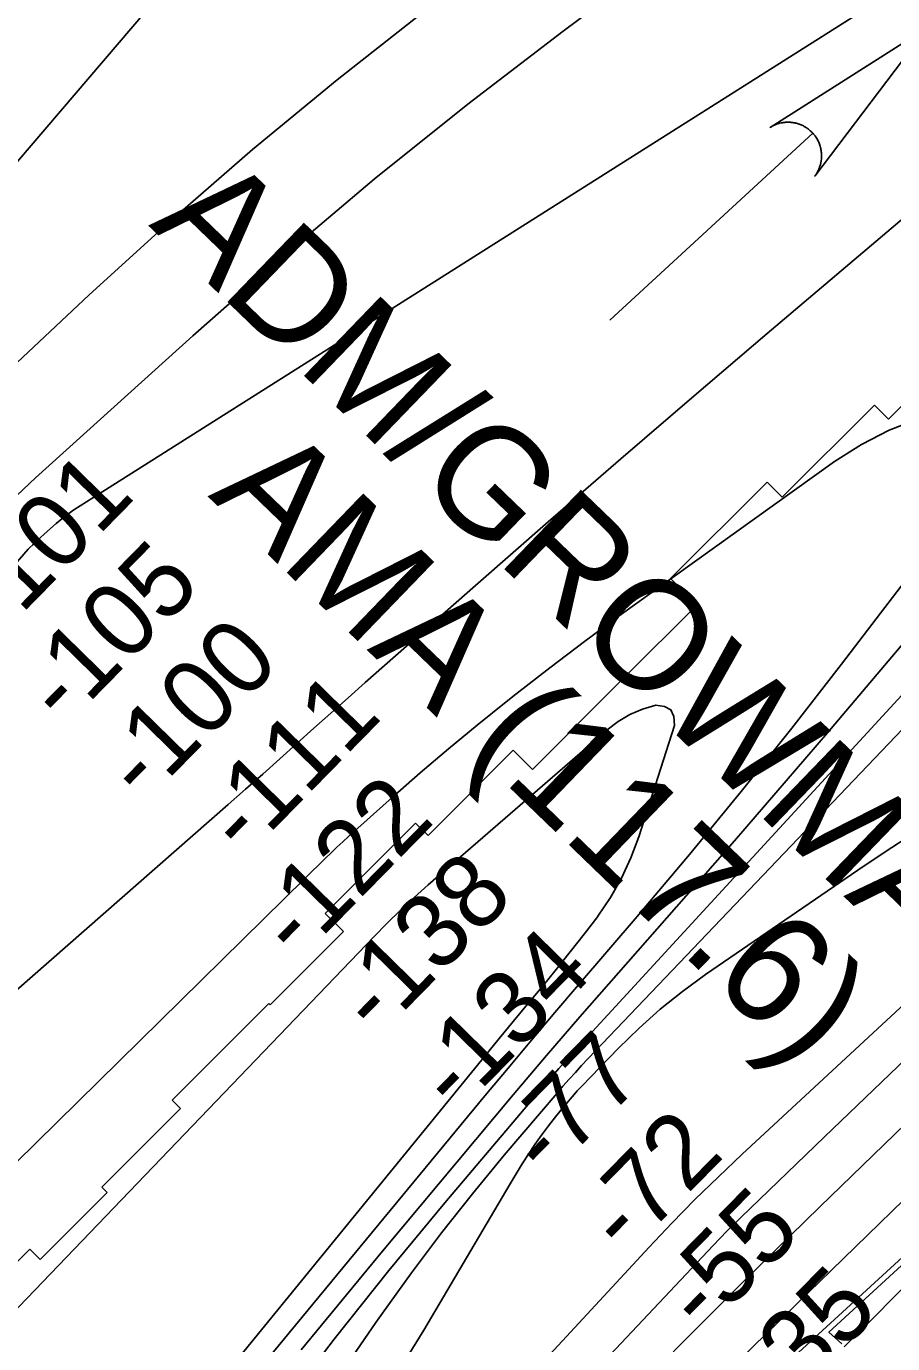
# Model space of a CAD drawing. Extents: x 3598634 to 3636690, y 517270 to 542944.
# Drawn here: x 3604038 to 3604825, y 525564 to 526759 of the extents above; entities that cross this region are included whole.
import ezdxf

# ---------------------------------------------------------------- set-up
doc = ezdxf.new("R2010")
doc.units = 0
for name, color, linetype in [('V-CHAN-DOCK', 7, 'Continuous'), ('V-CHAN-NAID', 7, 'Continuous'), ('V-RIVR-RANG', 7, 'Continuous'), ('V-RRAP-RVMT', 7, 'Continuous'), ('V-STRM-FLOW', 7, 'Continuous'), ('V-TOPO-DPTH', 7, 'Continuous'), ('V-TOPO-MAJR', 7, 'Continuous'), ('V-TOPO-MINR', 7, 'Continuous')]:
    doc.layers.add(name, color=color, linetype=linetype)

msp = doc.modelspace()

# ---------------------------------------------------------------- linework, layer by layer
at = {"layer": 'V-CHAN-DOCK'}
msp.add_lwpolyline([(3604778.3, 525563.9), (3604766.7, 525574.4), (3604858.4, 525658.5), (3604866.7, 525649.7), (3604886.5, 525666.4), (3604878.2, 525676.6), (3604978.3, 525768.3), (3604983, 525762.9), (3604995.7, 525775.9), (3604982.7, 525788.5), (3604971.2, 525776.7), (3604975.1, 525772.1), (3604688.2, 525509.3)], dxfattribs=at)
at = {"layer": 'V-RRAP-RVMT'}
for p, q in [((3604898.3, 526480.6), (3604820.7, 526403)), ((3604808, 526415.7), (3604724.4, 526332)), ((3604820.7, 526403), (3604808, 526415.7)), ((3604710.6, 526345.8), (3604622.9, 526258.2)), ((3604724.4, 526332), (3604710.6, 526345.8)), ((3604622.9, 526258.2), (3604646.8, 526234.2)), ((3604646.8, 526234.2), (3604580.4, 526167.8)), ((3604580.3, 526167.8), (3604497.6, 526085.1)), ((3604580.4, 526167.8), (3604580.3, 526167.8)), ((3604480.3, 526102.4), (3604403, 526025.1)), ((3604497.6, 526085.1), (3604480.3, 526102.4)), ((3604391.7, 526036.4), (3604309.7, 525954.4)), ((3604403, 526025.1), (3604391.7, 526036.4)), ((3604309.7, 525954.4), (3604326.1, 525938)), ((3604326.1, 525938), (3604259.6, 525871.5)), ((3604258.5, 525872.7), (3604170.8, 525785)), ((3604259.6, 525871.5), (3604258.5, 525872.7)), ((3604178.3, 525777.4), (3604106.9, 525706)), ((3604170.8, 525785), (3604178.3, 525777.4)), ((3604106.9, 525706), (3604111.7, 525701.2)), ((3604111.7, 525701.2), (3604050.9, 525640.4)), ((3604041.5, 525649.8), (3603970.1, 525578.4)), ((3604050.9, 525640.4), (3604041.5, 525649.8))]:
    msp.add_line(p, q, dxfattribs=at)
at = {"layer": 'V-STRM-FLOW'}
msp.add_line((3604567.8, 526492.9), (3604752, 526662.5), dxfattribs=at)
msp.add_lwpolyline([(3604713.3, 526667.7), (3604856.2, 526758.4), (3604753.9, 526623.5), (3604755.6, 526626), (3604757, 526628.6), (3604757.5, 526629.7), (3604757.9, 526630.7), (3604758.3, 526631.8), (3604758.7, 526633), (3604759, 526634), (3604759.4, 526635.4), (3604759.6, 526637), (3604759.8, 526637.8), (3604759.9, 526638.9), (3604760, 526640.4), (3604760, 526641.5), (3604760, 526642.8), (3604760, 526643.6), (3604759.9, 526644.5), (3604759.8, 526645.6), (3604759.7, 526646.6), (3604759.5, 526647.6), (3604759.3, 526648.4), (3604759.1, 526649.5), (3604758.7, 526650.7), (3604758.5, 526651.6), (3604758.1, 526652.6), (3604757.7, 526653.5), (3604757.4, 526654.3), (3604757.1, 526654.9), (3604756.7, 526655.8), (3604756.2, 526656.7), (3604755.7, 526657.5), (3604755.2, 526658.4), (3604754.7, 526659.1), (3604754.1, 526660), (3604753.6, 526660.6), (3604752.8, 526661.5), (3604752, 526662.5), (3604751.7, 526662.8), (3604751.3, 526663.3), (3604750.7, 526663.8), (3604750.2, 526664.3), (3604749.7, 526664.7), (3604749.2, 526665.2), (3604748.6, 526665.7), (3604748.2, 526666), (3604747.5, 526666.5), (3604746.9, 526667), (3604746.5, 526667.2), (3604745.3, 526668), (3604744.7, 526668.3), (3604744.3, 526668.6), (3604743.5, 526669), (3604742.9, 526669.3), (3604742.2, 526669.6), (3604741.4, 526670), (3604740.6, 526670.3), (3604740, 526670.5), (3604739.5, 526670.7), (3604738.7, 526670.9), (3604738.1, 526671.1), (3604737.3, 526671.4), (3604736.5, 526671.6), (3604735.7, 526671.7), (3604734.7, 526671.9), (3604734, 526672), (3604733.2, 526672.1), (3604732.4, 526672.2), (3604731.7, 526672.3), (3604731, 526672.3), (3604730, 526672.4), (3604729.9, 526672.4), (3604729.3, 526672.4), (3604728.9, 526672.4), (3604728.2, 526672.3), (3604727.3, 526672.3), (3604726.6, 526672.2), (3604726, 526672.2), (3604725.3, 526672.1), (3604724.5, 526671.9), (3604724, 526671.9), (3604723.3, 526671.7), (3604722.3, 526671.5), (3604721.8, 526671.4), (3604721.3, 526671.2), (3604720.9, 526671.1), (3604720.5, 526671), (3604719.8, 526670.8), (3604719.2, 526670.6), (3604718.6, 526670.3), (3604718, 526670.1), (3604717.2, 526669.8), (3604716.8, 526669.6), (3604716.1, 526669.2), (3604715.2, 526668.8), (3604714.6, 526668.5), (3604714.2, 526668.2), (3604713.8, 526668), (3604713.5, 526667.8)], close=True, dxfattribs=at)
at = {"layer": 'V-TOPO-DPTH'}
for points in [[(3604780.6, 525561.1), (3604792, 525572.4), (3604803.4, 525583.7), (3605198.6, 525983.2)], [(3605198.6, 525983.2), (3604803.4, 525583.7), (3604792, 525572.4), (3604780.6, 525561.1)], [(3604315.4, 525188.8), (3604720.6, 525583.5), (3604730, 525592.6), (3604739.3, 525601.8), (3604748.7, 525610.9), (3604758.1, 525620), (3604878.3, 525736.7)], [(3604315.4, 525188.8), (3604720.6, 525583.5), (3604730, 525592.6), (3604739.3, 525601.8), (3604748.7, 525610.9), (3604758.1, 525620), (3604878.3, 525736.7)]]:
    msp.add_lwpolyline(points, dxfattribs=at)
at = {"layer": 'V-TOPO-MAJR'}
for points in [[(3605519.2, 527085.7), (3605500.7, 527048.2), (3605480.6, 527011.4), (3605288.6, 526685.1), (3605269.7, 526654.7), (3605249.8, 526625), (3605228.4, 526596.3), (3605206.1, 526568.3), (3605180.6, 526537.9), (3605144.5, 526495.5), (3605108, 526453.4), (3605071, 526411.8), (3605033.5, 526370.6), (3604541.9, 525836.1), (3604531.7, 525824.9), (3604521.6, 525813.6), (3604511.7, 525802.2), (3604501.9, 525790.7), (3604418.3, 525691.8), (3604367.5, 525630.2), (3604317.7, 525567.9), (3604269.3, 525504.4)], [(3604026.2, 526268.9), (3604040.2, 526284.9), (3604041.5, 526286.3), (3604044.2, 526289), (3604045.6, 526290.3), (3604060.4, 526303.7), (3604065.5, 526308.2), (3604070.7, 526312.5), (3604076.1, 526316.6), (3604081.5, 526320.6), (3604087.2, 526324.3), (3604092.9, 526328), (3604098.7, 526331.4), (3604890.7, 526832.8)], [(3604600.5, 525531.3), (3604651.8, 525582.9), (3604678.3, 525609.3), (3604704.9, 525635.7), (3604731.6, 525661.9), (3604758.4, 525688), (3605476.3, 526383.5)]]:
    msp.add_lwpolyline(points, dxfattribs=at)
at = {"layer": 'V-TOPO-MINR'}
for points in [[(3603365.2, 525559), (3603379.7, 525577), (3603466.6, 525686.3), (3603525, 525758.6), (3603584.1, 525830.2), (3603644.4, 525901), (3603705.4, 525971.1), (3603980.8, 526282.8), (3603996.7, 526300.1), (3604012.9, 526317.1), (3604029.7, 526333.5), (3604046.8, 526349.6), (3604189.4, 526478.6), (3604271.1, 526550.5), (3604354.2, 526620.8), (3604439.2, 526688.7), (3604525.5, 526755.1), (3604676.3, 526867.6)], [(3604186.6, 526819.7), (3604108.5, 526728.2), (3604030.3, 526636.8), (3603900.4, 526485.1), (3603887.1, 526469.6), (3603873.9, 526454), (3603860.7, 526438.4), (3603847.5, 526422.8), (3603734.4, 526289), (3603664.3, 526206.8), (3603593.8, 526125), (3603522.5, 526043.9), (3603450.8, 525963.1), (3603228.2, 525714.8), (3603215.1, 525700.8), (3603201.7, 525687.1), (3603187.7, 525674), (3603173.3, 525661.2), (3602827.3, 525417.7)], [(3604398.5, 526772.4), (3604320.5, 526710.8), (3604243.7, 526647.6), (3604168.8, 526582.2), (3604095.1, 526515.3), (3603974.8, 526402.7), (3603962.5, 526390.8), (3603950.3, 526378.7), (3603938.6, 526366.3), (3603927, 526353.6), (3603792.2, 526201.1), (3603713.7, 526111.7), (3603635.7, 526021.9), (3603558.3, 525931.6), (3603481.4, 525840.9), (3603317.9, 525646.5), (3603300.8, 525626.5), (3603283.7, 525606.6), (3603266.3, 525586.9), (3603248.9, 525567.3), (3603163.5, 525472.5)], [(3605247.7, 526750.2), (3605248.1, 526745.1), (3605247.3, 526739.7), (3605245.3, 526734.1), (3605243, 526728.7), (3605240.3, 526723.4), (3605237.4, 526718.2), (3605208.3, 526670.9), (3605205.9, 526667.2), (3605203.5, 526663.5), (3605200.9, 526660), (3605198.2, 526656.5), (3605011.6, 526418.4), (3604930.9, 526317.2), (3604849, 526216.9), (3604765.5, 526118.1), (3604680.9, 526020.1), (3604540.8, 525860.6), (3604525.5, 525843), (3604510.3, 525825.4), (3604495.2, 525807.6), (3604480.2, 525789.8), (3604361.5, 525647.7), (3604287.8, 525558.3)], [(3603645.9, 525546.6), (3603724.9, 525616.6), (3603804, 525686.5), (3603883.2, 525756.3), (3603962.5, 525826), (3604221.7, 526053.3), (3604237.3, 526067), (3604252.9, 526080.8), (3604268.4, 526094.7), (3604283.9, 526108.5), (3604299.3, 526122.4), (3604314.8, 526136.2), (3604330.4, 526150), (3604346, 526163.8), (3604446.1, 526252), (3604511.9, 526309.6), (3604577.9, 526367), (3604644.3, 526424), (3604710.8, 526480.7), (3604835, 526585.8)], [(3603728.8, 525433.1), (3604310, 526004.4), (3604315.1, 526009.4), (3604320.3, 526014.4), (3604325.6, 526019.3), (3604330.9, 526024.1), (3604370.5, 526059.6), (3604395.8, 526081.9), (3604421.4, 526103.8), (3604447.5, 526125.3), (3604473.8, 526146.4), (3604482.5, 526153.2), (3604513.6, 526177.3), (3604544.9, 526201.1), (3604576.5, 526224.4), (3604608.3, 526247.5), (3604771.9, 526364.5), (3604796.2, 526379.8), (3604821.4, 526393), (3604848, 526403.2)], [(3604863.7, 526292.5), (3604778.2, 526180.7), (3604732.9, 526122.5), (3604687, 526064.9), (3604640.1, 526007.9), (3604592.6, 525951.5), (3604539.5, 525889.6), (3604518.1, 525864.5), (3604496.8, 525839.3), (3604475.7, 525814), (3604454.6, 525788.7), (3604223.9, 525509.5)], [(3603702.1, 525254), (3604354.1, 525933.5), (3604366, 525945.6), (3604378.1, 525957.4), (3604390.5, 525968.9), (3604403.2, 525980.2), (3604565.6, 526121.1), (3604575.6, 526128.6), (3604586.2, 526135), (3604597.6, 526139.8), (3604609.6, 526143.5), (3604617.6, 526142.3), (3604623.4, 526139.2), (3604626.1, 526133.1), (3604626.6, 526125), (3604594.2, 526023.9), (3604587, 526004.9), (3604578.6, 525986.4), (3604568.4, 525968.9), (3604557, 525952), (3604556.9, 525951.7), (3604544.5, 525935.5), (3604532, 525919.4), (3604519.3, 525903.6), (3604506.4, 525887.8), (3604493.3, 525872.1), (3604480.3, 525856.4), (3604467.4, 525840.7), (3604454.5, 525824.9), (3604042.5, 525320)], [(3604839.8, 526128.2), (3604542.3, 525816.2), (3604536.6, 525810.1), (3604531, 525803.9), (3604525.4, 525797.6), (3604520, 525791.3), (3604472.1, 525735), (3604443.3, 525700), (3604415.1, 525664.5), (3604388, 525628.3), (3604361.5, 525591.5), (3604355.7, 525583.2), (3604327.1, 525541.7)], [(3604353.2, 525501.8), (3604399.2, 525576.2), (3604477.4, 525709.1), (3604482.8, 525718.1), (3604488.3, 525727), (3604494, 525735.8), (3604499.8, 525744.6), (3604505.9, 525753.2), (3604512.1, 525761.6), (3604518.6, 525769.8), (3604525.2, 525777.9), (3604537, 525791.8), (3604538.3, 525793.3), (3604539.7, 525794.8), (3604542.4, 525797.7), (3604575.8, 525832.1), (3604594.4, 525850.2), (3604613.7, 525867.4), (3604633.9, 525883.5), (3604654.8, 525898.8), (3604793, 525993.5), (3604817.7, 526010.2), (3604842.7, 526026.6)], [(3604145.6, 525156.5), (3604603.7, 525651.6), (3604624.2, 525673.3), (3604645, 525694.6), (3604666.4, 525715.4), (3604688, 525735.9), (3604958, 525986.1)], [(3604780.6, 525561.1), (3604792, 525572.4), (3604803.4, 525583.7), (3605198.6, 525983.2)], [(3604524, 525506.8), (3604661.8, 525653.1), (3604667.9, 525659.5), (3604674.2, 525665.9), (3604680.5, 525672.2), (3604686.9, 525678.4), (3604762.8, 525751.5), (3604807.2, 525794.2), (3604851.6, 525836.9)], [(3604315.4, 525188.8), (3604720.6, 525583.5), (3604730, 525592.6), (3604739.3, 525601.8), (3604748.7, 525610.9), (3604758.1, 525620), (3604878.3, 525736.7)]]:
    msp.add_lwpolyline(points, dxfattribs=at)

# ---------------------------------------------------------------- texts
at = {"layer": 'V-CHAN-NAID'}
for s, p in [('ADM/GROWMARK ', (3604148.8, 526578.8)), (' AMA (117.6)', (3604175.9, 526358.9))]:
    msp.add_text(s, height=100, rotation=316.027, dxfattribs=at).set_placement(p)
at = {"layer": 'V-RIVR-RANG'}
for s, p in [('-101', (3604012.9, 526203.9)), ('-105', (3604073.3, 526122.7)), ('-100', (3604145.1, 526053.1)), ('-111', (3604237, 526004)), ('-122', (3604284.8, 525909.9)), ('-138', (3604357.2, 525840.9)), ('-134', (3604429, 525771.3)), ('-77', (3604511.1, 525712.2)), ('-72', (3604582.4, 525642.1)), ('-55', (3604653.2, 525571.5)), ('-35', (3604723.4, 525500.2))]:
    msp.add_text(s, height=67, rotation=45.5823, dxfattribs=at).set_placement(p)

doc.saveas('drawing.dxf')
